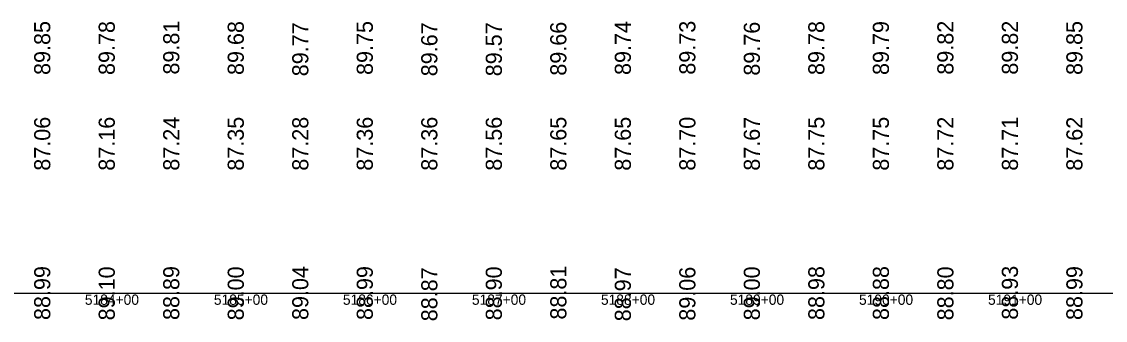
# Model space of a CAD drawing. Extents: x 2147288 to 2220488, y 740833 to 759333.
# Drawn here: x 2200708 to 2201548, y 750062 to 750294 of the extents above; entities that cross this region are included whole.
import ezdxf

# ---------------------------------------------------------------- set-up
doc = ezdxf.new("R2010")
doc.units = 0
for name, color, linetype in [('RD_DDB_Profile_EX', 7, 'Continuous'), ('RD_DDB_StaTX', 7, 'Continuous'), ('RD_DDB_StripGrade', 7, 'Continuous'), ('RD_GPK_Profile_Cell', 7, 'Continuous')]:
    doc.layers.add(name, color=color, linetype=linetype)

msp = doc.modelspace()

# ---------------------------------------------------------------- linework, layer by layer
at = {"layer": 'RD_GPK_Profile_Cell'}
msp.add_line((2198888.28, 750083.43), (2220488.28, 750083.43), dxfattribs=at)

# ---------------------------------------------------------------- texts
at = {"layer": 'RD_DDB_Profile_EX'}
for s, p in [('89.85', (2200730.08, 750252.69)), ('89.81', (2200830.08, 750253)), ('89.75', (2200980.08, 750252.69)), ('89.74', (2201180.08, 750252.66)), ('89.73', (2201230.08, 750252.89)), ('89.82', (2201430.08, 750252.89)), ('89.82', (2201480.08, 750252.89)), ('89.85', (2201530.08, 750252.69)), ('89.78', (2200780.08, 750252.64)), ('89.68', (2200880.08, 750252.64)), ('89.77', (2200930.08, 750251.67)), ('89.67', (2201030.08, 750251.67)), ('89.57', (2201080.08, 750251.67)), ('89.66', (2201130.08, 750252.13)), ('89.76', (2201280.08, 750252.13)), ('89.78', (2201330.08, 750252.64)), ('89.79', (2201380.08, 750252.64)), ('88.99', (2200730.08, 750062.64)), ('89.10', (2200780.08, 750062.38)), ('88.89', (2200830.08, 750062.64)), ('89.00', (2200880.08, 750062.38)), ('89.04', (2200930.08, 750062.66)), ('88.99', (2200980.08, 750062.64)), ('88.87', (2201030.08, 750061.67)), ('88.90', (2201080.08, 750062.38)), ('88.81', (2201130.08, 750063)), ('88.97', (2201180.08, 750061.67)), ('89.06', (2201230.08, 750062.13)), ('89.00', (2201280.08, 750062.38)), ('88.98', (2201330.08, 750062.64)), ('88.88', (2201380.08, 750062.64)), ('88.80', (2201430.08, 750062.38)), ('88.93', (2201480.08, 750062.89)), ('88.99', (2201530.08, 750062.64))]:
    msp.add_text(s, height=12.5, rotation=90, dxfattribs=at).set_placement(p)
at = {"layer": 'RD_DDB_StaTX'}
for s, p in [('5184+00', (2200756.88, 750074.43)), ('5184+00', (2200756.88, 750074.43)), ('5184+00', (2200756.88, 750074.43)), ('5185+00', (2200856.88, 750074.43)), ('5185+00', (2200856.88, 750074.43)), ('5185+00', (2200856.88, 750074.43)), ('5186+00', (2200956.88, 750074.43)), ('5186+00', (2200956.88, 750074.43)), ('5186+00', (2200956.88, 750074.43)), ('5187+00', (2201056.88, 750074.43)), ('5187+00', (2201056.88, 750074.43)), ('5187+00', (2201056.88, 750074.43)), ('5188+00', (2201156.88, 750074.43)), ('5188+00', (2201156.88, 750074.43)), ('5188+00', (2201156.88, 750074.43)), ('5189+00', (2201256.88, 750074.43)), ('5189+00', (2201256.88, 750074.43)), ('5189+00', (2201256.88, 750074.43)), ('5190+00', (2201356.88, 750074.43)), ('5190+00', (2201356.88, 750074.43)), ('5190+00', (2201356.88, 750074.43)), ('5191+00', (2201456.88, 750074.43)), ('5191+00', (2201456.88, 750074.43)), ('5191+00', (2201456.88, 750074.43))]:
    msp.add_text(s, height=8, dxfattribs=at).set_placement(p)
at = {"layer": 'RD_DDB_StripGrade'}
for s, p in [('87.06', (2200730.08, 750178.43)), ('87.16', (2200780.08, 750178.43)), ('87.24', (2200830.08, 750178.43)), ('87.35', (2200880.08, 750178.43)), ('87.28', (2200930.08, 750178.43)), ('87.36', (2200980.08, 750178.43)), ('87.36', (2201030.08, 750178.43)), ('87.56', (2201080.08, 750178.43)), ('87.65', (2201130.08, 750178.43)), ('87.65', (2201180.08, 750178.43)), ('87.70', (2201230.08, 750178.43)), ('87.67', (2201280.08, 750178.43)), ('87.75', (2201330.08, 750178.43)), ('87.75', (2201380.08, 750178.43)), ('87.72', (2201430.08, 750178.43)), ('87.71', (2201480.08, 750178.43)), ('87.62', (2201530.08, 750178.43))]:
    msp.add_text(s, height=12.5, rotation=90, dxfattribs=at).set_placement(p)

doc.saveas('drawing.dxf')
